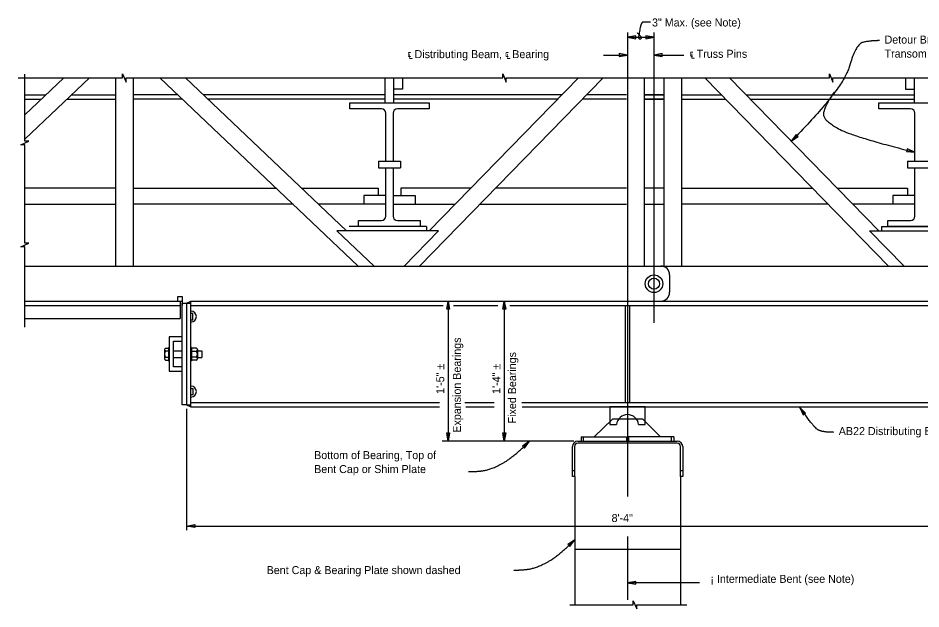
# Model space of a CAD drawing. Extents: x 0.1 to 14.7, y 0.1 to 9.6.
# Drawn here: x 0.1 to 8.63, y 3.97 to 9.55 of the extents above; entities that cross this region are included whole.
import ezdxf

# ---------------------------------------------------------------- set-up
doc = ezdxf.new("R2010")
doc.units = 0
for name, color, linetype in [('CL_Minor', 7, 'Continuous'), ('Dimension', 7, 'Continuous'), ('SteelMisc', 7, 'Continuous'), ('SteelMisc_h', 7, 'Continuous'), ('Symbols', 7, 'Continuous'), ('TextStructures', 7, 'Continuous'), ('Wood', 7, 'Continuous')]:
    doc.layers.add(name, color=color, linetype=linetype)

msp = doc.modelspace()

# ---------------------------------------------------------------- linework, layer by layer
at = {"layer": 'CL_Minor'}
for p, q in [((5.8623, 9.4137), (5.8623, 5.0314)), ((6.1123, 6.6717), (6.1123, 9.4137)), ((5.8623, 4.6544), (5.8623, 4.0558))]:
    msp.add_line(p, q, dxfattribs=at)
at = {"layer": 'Dimension'}
for p, q in [((5.8623, 9.3686), (6.1123, 9.3686)), ((5.6358, 9.2013), (5.8623, 9.2013)), ((6.1123, 9.2013), (6.3925, 9.2013)), ((4.1683, 6.8771), (4.1683, 5.5542)), ((4.6981, 6.8771), (4.6981, 5.5542)), ((1.6956, 5.8602), (1.6956, 4.7139)), ((5.3557, 5.5542), (4.1123, 5.5542)), ((1.6956, 4.7517), (10.029, 4.7517))]:
    msp.add_line(p, q, dxfattribs=at)
for points in [[(5.8623, 9.3686), (5.9404, 9.3554), (5.9404, 9.3818)], [(6.1123, 9.3686), (6.0342, 9.3818), (6.0342, 9.3554)], [(5.8623, 9.2013), (5.7842, 9.2146), (5.7842, 9.1881)], [(6.1123, 9.2013), (6.1904, 9.1881), (6.1904, 9.2146)], [(7.4096, 8.3866), (7.4738, 8.433), (7.4549, 8.4516)], [(8.5774, 8.2833), (8.5048, 8.3151), (8.4984, 8.2894)], [(4.1551, 6.799), (4.1683, 6.8771), (4.1815, 6.799)], [(4.6848, 6.799), (4.6981, 6.8771), (4.7113, 6.799)], [(7.4886, 5.873), (7.523, 5.8016), (7.5446, 5.8169)], [(4.1815, 5.6323), (4.1683, 5.5542), (4.1551, 5.6323)], [(4.7113, 5.6323), (4.6981, 5.5542), (4.6848, 5.6323)], [(4.936, 5.5526), (4.8711, 5.5071), (4.8897, 5.4883)], [(1.7737, 4.7385), (1.6956, 4.7517), (1.7737, 4.765)], [(5.3641, 4.6221), (5.2992, 4.5767), (5.3178, 4.5579)], [(5.8623, 4.2159), (5.9404, 4.2027), (5.9404, 4.2291)]]:
    msp.add_lwpolyline(points, close=True, dxfattribs=at)
for points in [[(6.0779, 9.5128), (6.0252, 9.5128), (5.9999, 9.5128), (5.9831, 9.4748), (5.9662, 9.3736), (5.9662, 9.3547), (5.9936, 9.3547), (5.9936, 9.3715), (5.9557, 9.4105)], [(8.2422, 9.3373), (8.1495, 9.3373), (8.0188, 9.3036), (7.8986, 8.8841), (7.4096, 8.3866)], [(7.8131, 8.8507), (7.7131, 8.7007), (7.7131, 8.5848), (7.9871, 8.4309), (8.5774, 8.2833)], [(7.8111, 5.6369), (7.6994, 5.6369), (7.6214, 5.6854), (7.4886, 5.873)], [(4.3605, 5.2659), (4.4533, 5.2659), (4.5776, 5.2891), (4.7737, 5.3924), (4.936, 5.5526)], [(4.7886, 4.3355), (4.8814, 4.3355), (5.0057, 4.3586), (5.2018, 4.4619), (5.3641, 4.6221)]]:
    msp.add_open_spline(points, degree=2, dxfattribs=at)
at = {"layer": 'SteelMisc'}
for p, q in [((0.7792, 8.9852), (0.1675, 8.4052)), ((0.5369, 8.9852), (0.1675, 8.6349)), ((1.029, 7.2078), (1.029, 8.9852)), ((1.1956, 7.2078), (1.1956, 8.9852)), ((1.4448, 8.9852), (3.3157, 7.2078)), ((1.6868, 8.9852), (3.207, 7.5411)), ((3.5718, 8.7495), (3.5718, 8.9852)), ((3.6527, 8.7495), (3.6527, 8.9852)), ((3.8958, 7.2078), (5.631, 8.9852)), ((3.9882, 7.5411), (5.3981, 8.9852)), ((6.0185, 8.9852), (6.0185, 7.2078)), ((6.2061, 8.9852), (6.2061, 7.2078)), ((6.3727, 8.9852), (6.3727, 7.2078)), ((8.3288, 7.2078), (6.5936, 8.9852)), ((8.2364, 7.5411), (6.8265, 8.9852)), ((8.5718, 8.7495), (8.5718, 8.9852)), ((0.1675, 8.8247), (0.3676, 8.8247)), ((0.6099, 8.8247), (1.029, 8.8247)), ((1.6138, 8.8247), (1.1956, 8.8247)), ((3.5718, 8.8247), (1.8558, 8.8247)), ((5.2413, 8.8247), (3.6527, 8.8247)), ((5.8518, 8.8247), (5.4743, 8.8247)), ((6.2061, 8.8247), (6.0185, 8.8247)), ((6.0185, 8.8247), (6.2061, 8.8247)), ((6.3727, 8.8247), (6.7503, 8.8247)), ((6.9833, 8.8247), (8.5718, 8.8247)), ((0.1675, 8.783), (0.3237, 8.783)), ((0.5659, 8.783), (1.029, 8.783)), ((1.6576, 8.783), (1.1956, 8.783)), ((3.5718, 8.783), (1.8997, 8.783)), ((3.2374, 8.6936), (3.2374, 8.7495)), ((3.2374, 8.7495), (3.9873, 8.7495)), ((5.2006, 8.783), (3.6527, 8.783)), ((3.9873, 8.7495), (3.9873, 8.6936)), ((5.8518, 8.783), (5.4336, 8.783)), ((6.0185, 8.783), (6.2061, 8.783)), ((6.2061, 8.783), (6.0185, 8.783)), ((6.3727, 8.783), (6.791, 8.783)), ((7.024, 8.783), (8.5718, 8.783)), ((8.2372, 8.6936), (8.2372, 8.7495)), ((8.2372, 8.7495), (8.9871, 8.7495)), ((3.5365, 8.6936), (3.2374, 8.6936)), ((3.5782, 8.1974), (3.5782, 8.6519)), ((3.6466, 8.6519), (3.6466, 8.1974)), ((3.9873, 8.6936), (3.6883, 8.6936)), ((8.5363, 8.6936), (8.2372, 8.6936)), ((8.578, 8.1974), (8.578, 8.6519)), ((3.5083, 8.1974), (3.5083, 8.1349)), ((3.5083, 8.1974), (3.7166, 8.1974)), ((3.7166, 8.1974), (3.7166, 8.1349)), ((8.5081, 8.1974), (8.5081, 8.1349)), ((8.5081, 8.1974), (8.7164, 8.1974)), ((3.5083, 8.1349), (3.7166, 8.1349)), ((3.5782, 7.6804), (3.5782, 8.1349)), ((3.6466, 8.1349), (3.6466, 7.6804)), ((8.5081, 8.1349), (8.7164, 8.1349)), ((8.578, 7.6804), (8.578, 8.1349)), ((3.5061, 7.9436), (3.5061, 7.8745)), ((3.7187, 7.9436), (3.7187, 7.8745)), ((8.5059, 7.9436), (8.5059, 7.8745)), ((3.3699, 7.8745), (3.3699, 7.7936)), ((3.5782, 7.8745), (3.3699, 7.8745)), ((3.6466, 7.8745), (3.8549, 7.8745)), ((3.8549, 7.8745), (3.8549, 7.7936)), ((8.3697, 7.8745), (8.3697, 7.7936)), ((8.578, 7.8745), (8.3697, 7.8745)), ((3.3207, 7.5828), (3.3207, 7.6387)), ((3.3207, 7.6387), (3.5365, 7.6387)), ((3.6883, 7.6387), (3.904, 7.6387)), ((3.904, 7.6387), (3.904, 7.5828)), ((8.3205, 7.5828), (8.3205, 7.6387)), ((8.3205, 7.6387), (8.5363, 7.6387)), ((4.0756, 7.5411), (3.1162, 7.5411)), ((3.1162, 7.5411), (3.467, 7.2078)), ((3.964, 7.5828), (3.2314, 7.5828)), ((3.7502, 7.2078), (4.0756, 7.5411)), ((3.964, 7.5828), (3.964, 7.5422)), ((8.4744, 7.2078), (8.149, 7.5411)), ((8.149, 7.5411), (9.1084, 7.5411)), ((8.2606, 7.5828), (8.9931, 7.5828)), ((8.2606, 7.5828), (8.2606, 7.5422)), ((0.1675, 7.2078), (14.6363, 7.2078)), ((6.2599, 7.1245), (6.2599, 6.9604)), ((0.1675, 6.8771), (1.6547, 6.8771)), ((1.6343, 6.8771), (1.6343, 6.7131)), ((1.6956, 6.8563), (1.7373, 6.8771)), ((1.6956, 6.8563), (1.7373, 6.8563)), ((1.7373, 5.8771), (1.7373, 6.8771)), ((1.7373, 6.8771), (9.9873, 6.8771)), ((1.7373, 6.8362), (4.119, 6.8362)), ((4.2191, 6.8362), (4.6363, 6.8362)), ((4.7489, 6.8362), (9.9873, 6.8362)), ((5.8414, 5.9181), (5.8414, 6.8362)), ((5.8831, 5.9181), (5.8831, 6.8362)), ((1.7553, 6.7608), (1.7373, 6.7608)), ((1.7553, 6.6995), (1.7553, 6.7608)), ((0.1675, 6.7131), (1.6343, 6.7131)), ((1.7373, 6.6995), (1.7553, 6.6995)), ((1.4875, 6.418), (1.4875, 6.3339)), ((1.498, 6.4331), (1.5265, 6.4331)), ((1.5265, 6.4045), (1.498, 6.4045)), ((1.5265, 6.4385), (1.5322, 6.4385)), ((1.5265, 6.4385), (1.5265, 6.3135)), ((1.5731, 6.4072), (1.6547, 6.4072)), ((1.7429, 6.4385), (1.7373, 6.4385)), ((1.7429, 6.4385), (1.7429, 6.3135)), ((1.7873, 6.4331), (1.7429, 6.4331)), ((1.7429, 6.4045), (1.7873, 6.4045)), ((1.7978, 6.418), (1.7978, 6.3339)), ((1.7978, 6.4072), (1.84, 6.4072)), ((1.84, 6.4072), (1.84, 6.3448)), ((1.498, 6.3474), (1.5265, 6.3474)), ((1.498, 6.3189), (1.5265, 6.3189)), ((1.5265, 6.3135), (1.5322, 6.3135)), ((1.5731, 6.3448), (1.6547, 6.3448)), ((1.7429, 6.3135), (1.7373, 6.3135)), ((1.7873, 6.3474), (1.7429, 6.3474)), ((1.7873, 6.3189), (1.7429, 6.3189)), ((1.7978, 6.3448), (1.84, 6.3448)), ((1.7373, 6.0524), (1.7553, 6.0524)), ((1.7553, 5.9911), (1.7373, 5.9911)), ((1.7553, 5.9911), (1.7373, 5.9911)), ((1.7553, 6.0524), (1.7553, 5.9911)), ((1.6956, 5.898), (1.7373, 5.898)), ((1.6956, 5.898), (1.7373, 5.8771)), ((1.7373, 5.9181), (4.0841, 5.9181)), ((4.326, 5.9181), (4.6013, 5.9181)), ((4.862, 5.9181), (9.9873, 5.9181)), ((1.7373, 5.8771), (4.0841, 5.8771)), ((4.3344, 5.8771), (4.6013, 5.8771)), ((4.8662, 5.8771), (9.9873, 5.8771)), ((5.7191, 5.7625), (5.5471, 5.5958)), ((6.0055, 5.7625), (5.7191, 5.7625)), ((6.0055, 5.7625), (6.1722, 5.5958)), ((5.3935, 5.5542), (6.3311, 5.5542)), ((5.4248, 5.5959), (5.4248, 5.5542)), ((5.4248, 5.5959), (5.852, 5.5959)), ((5.4456, 5.5542), (5.4456, 5.5959)), ((5.852, 5.5959), (5.852, 5.5542)), ((6.2998, 5.5959), (5.8726, 5.5959)), ((5.8726, 5.5959), (5.8726, 5.5542)), ((6.2789, 5.5542), (6.2789, 5.5959)), ((6.2998, 5.5959), (6.2998, 5.5542)), ((5.3415, 5.2209), (5.3415, 5.5022)), ((5.3623, 5.5022), (5.3623, 5.2209)), ((6.3311, 5.5334), (5.3935, 5.5334)), ((6.3623, 5.2209), (6.3623, 5.5022)), ((6.3831, 5.5022), (6.3831, 5.2209)), ((5.3415, 5.2762), (5.3623, 5.2762)), ((5.3623, 5.2209), (5.3415, 5.2209)), ((6.3623, 5.2762), (6.3831, 5.2762)), ((6.3831, 5.2209), (6.3623, 5.2209))]:
    msp.add_line(p, q, dxfattribs=at)
for points in [[(3.7361, 8.9852), (3.7361, 8.8774), (3.6527, 8.8774), (3.6527, 8.9852)], [(8.4885, 8.9852), (8.4885, 8.8774), (8.5718, 8.8774), (8.5718, 8.9852)], [(1.029, 7.9436), (0.1675, 7.9436)], [(1.1956, 7.9436), (2.5439, 7.9436)], [(2.7862, 7.9436), (3.5061, 7.9436)], [(4.3811, 7.9436), (3.7187, 7.9436)], [(5.8518, 7.9436), (4.6141, 7.9436)], [(6.2061, 7.9436), (6.0185, 7.9436)], [(6.3727, 7.9436), (7.6105, 7.9436)], [(7.8435, 7.9436), (8.5059, 7.9436)], [(0.1675, 7.7936), (1.029, 7.7936)], [(2.7021, 7.7936), (1.1956, 7.7936)], [(3.5782, 7.7936), (2.9444, 7.7936)], [(3.6466, 7.7936), (4.2347, 7.7936)], [(4.4677, 7.7936), (5.8518, 7.7936)], [(6.0185, 7.7936), (6.2061, 7.7936)], [(7.7569, 7.7936), (6.3727, 7.7936)], [(8.578, 7.7936), (7.9899, 7.7936)], [(3.904, 7.5828), (3.6125, 7.5828), (3.3207, 7.5828)], [(8.9038, 7.5828), (8.6123, 7.5828), (8.3205, 7.5828)], [(1.6138, 6.8771), (1.6138, 6.9188), (1.6547, 6.9188), (1.6547, 6.8362)], [(5.9659, 5.7104), (6.0289, 5.7104), (6.0289, 5.8771), (5.6956, 5.8771), (5.6956, 5.7104), (5.7587, 5.7104)]]:
    msp.add_lwpolyline(points, dxfattribs=at)
for points in [[(1.6956, 5.898), (1.6547, 5.898), (1.6547, 6.8563), (1.6956, 6.8563)], [(1.6547, 6.5406), (1.5322, 6.5406), (1.5322, 6.2138), (1.6547, 6.2138), (1.6547, 6.2547), (1.5731, 6.2547), (1.5731, 6.4997), (1.6547, 6.4997)]]:
    msp.add_lwpolyline(points, close=True, dxfattribs=at)
for radius in [0.0833, 0.0521]:
    msp.add_circle((6.1123, 7.0411), radius, dxfattribs=at)
for centre, radius, start, end in [((3.5365, 8.6519), 0.0417, 0, 90), ((3.6883, 8.6519), 0.0417, 90, 180), ((8.5363, 8.6519), 0.0417, 0, 90), ((3.5365, 7.6804), 0.0417, 270, 360), ((3.6883, 7.6804), 0.0417, 180, 270), ((8.5363, 7.6804), 0.0417, 270, 360), ((6.1766, 7.1245), 0.0833, 0, 90), ((6.1766, 6.9604), 0.0833, 270, 0), ((1.7373, 6.7302), 0.0514, 270.02786, 89.97214), ((1.5024, 6.4188), 0.0149, 107.25576, 183.01536), ((1.5024, 6.4188), 0.0149, 183.01536, 252.74424), ((1.5316, 6.376), 0.0441, 139.64006, 220.35994), ((1.7829, 6.4188), 0.0149, 356.98464, 72.74424), ((1.7829, 6.4188), 0.0149, 287.25576, 356.98464), ((1.7537, 6.376), 0.0441, 319.64006, 40.35994), ((1.5024, 6.3331), 0.0149, 107.25576, 176.98464), ((1.5024, 6.3331), 0.0149, 176.98464, 252.74424), ((1.7829, 6.3331), 0.0149, 3.01536, 72.74424), ((1.7829, 6.3331), 0.0149, 287.25576, 3.01536), ((1.7373, 6.0218), 0.0514, 270.02786, 89.97214), ((5.8623, 5.7), 0.1042, 5.70323, 174.29677), ((5.3935, 5.5022), 0.052, 90, 180), ((6.3311, 5.5022), 0.052, 0, 90), ((5.3935, 5.5022), 0.0312, 90, 180), ((6.3311, 5.5022), 0.0312, 0, 90)]:
    msp.add_arc(centre, radius, start, end, dxfattribs=at)
at = {"layer": 'SteelMisc_h'}
msp.add_line((0.1675, 6.8362), (1.6343, 6.8362), dxfattribs=at)
at = {"layer": 'Symbols'}
for points in [[(0.1038, 8.9852), (1.0911, 8.9852), (1.0911, 9.024), (1.1248, 8.9465), (1.1248, 8.9852), (3.3324, 8.9852)], [(0.1675, 7.7688), (0.1675, 8.3524), (0.1287, 8.3524), (0.2062, 8.3861), (0.1675, 8.3861), (0.1675, 9.0201)], [(3.3324, 8.9852), (4.6826, 8.9852), (4.6826, 9.024), (4.7163, 8.9465), (4.7163, 8.9852), (6.1123, 8.9852)], [(6.1123, 8.9852), (7.7693, 8.9852), (7.7693, 9.024), (7.803, 8.9465), (7.803, 8.9852), (9.0387, 8.9852)], [(0.1675, 6.6318), (0.1675, 7.3892), (0.1287, 7.3892), (0.2062, 7.4229), (0.1675, 7.4229), (0.1675, 7.7688)], [(5.3184, 4.0072), (5.9152, 4.0072), (5.9152, 4.046), (5.9489, 3.9685), (5.9489, 4.0072), (6.4217, 4.0072)]]:
    msp.add_lwpolyline(points, dxfattribs=at)
at = {"layer": 'TextStructures'}
msp.add_line((6.541, 4.2159), (5.8623, 4.2159), dxfattribs=at)
at = {"layer": 'Wood'}
for p, q in [((5.3641, 5.2209), (5.3641, 4.0072)), ((6.3641, 5.2209), (6.3641, 4.0072)), ((5.3627, 4.5334), (6.3619, 4.5334))]:
    msp.add_line(p, q, dxfattribs=at)

# ---------------------------------------------------------------- texts
at = {"layer": 'Dimension'}
for s, p in [('1\'-5" ±', (4.1305, 6.0003)), ('1\'-4" ±', (4.6603, 6.0003))]:
    msp.add_text(s, height=0.0756, rotation=90, dxfattribs=at).set_placement(p)
msp.add_text('8\'-4"', height=0.0756, dxfattribs=at).set_placement((5.7114, 4.7895))
at = {"layer": 'TextStructures'}
for s, p in [('3" Max. (see Note)', (6.0936, 9.471)), ('Detour Bridge Superstructure (Truss and ', (8.2905, 9.3092)), ('℄ Distributing Beam, ℄ Bearing', (3.7807, 9.172)), ('℄ Truss Pins', (6.4462, 9.1751)), ('Transom members shown dotted)', (8.2905, 9.1772)), ('AB22 Distributing Beam', (7.8579, 5.6109)), ('Bottom of Bearing, Top of ', (2.9014, 5.384)), ('Bent Cap or Shim Plate', (2.9014, 5.252)), ('Bent Cap & Bearing Plate shown dashed', (2.4526, 4.2977)), ('¡ Intermediate Bent (see Note)', (6.6448, 4.215))]:
    msp.add_text(s, height=0.0756, dxfattribs=at).set_placement(p)
for s, p in [('Expansion Bearings', (4.2877, 5.6338)), ('Fixed Bearings', (4.8091, 5.7212))]:
    msp.add_text(s, height=0.0756, rotation=90, dxfattribs=at).set_placement(p)

doc.saveas('drawing.dxf')
